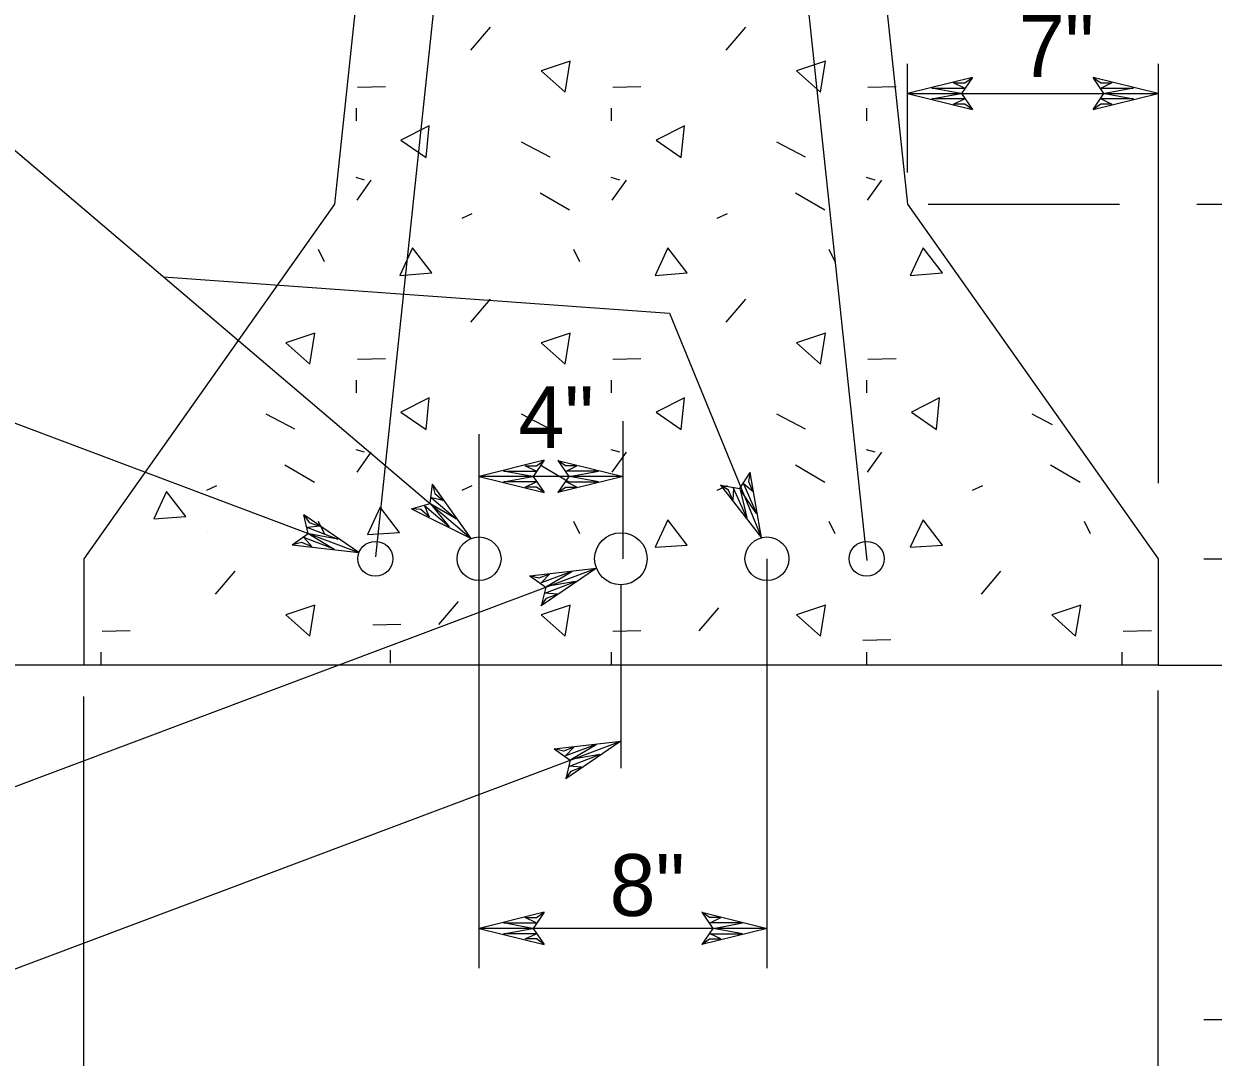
# Model space of a CAD drawing. Extents: x 504255 to 505955, y 659986 to 661086.
# Drawn here: x 504466.5 to 504576.9, y 660121 to 660217 of the extents above; entities that cross this region are included whole.
import ezdxf

# ---------------------------------------------------------------- set-up
doc = ezdxf.new("R2010")
doc.units = 0
for name, color, linetype in [('Level1', 7, 'Continuous'), ('Level3', 7, 'Continuous'), ('Level63', 7, 'Continuous')]:
    doc.layers.add(name, color=color, linetype=linetype)

msp = doc.modelspace()

# ---------------------------------------------------------------- linework, layer by layer
at = {"layer": 'Level1'}
for p, q in [((504548.54, 660203.18), (504548.54, 660213.27)), ((504571.81, 660213.27), (504571.81, 660174.33)), ((504459.95, 660210.08), (504508.05, 660169.2)), ((504548.54, 660210.51), (504571.81, 660210.51)), ((504550.46, 660200.24), (504568.25, 660200.24)), ((504575.42, 660200.24), (504641.43, 660200.24)), ((504552.13, 660193.73), (504552.13, 660193.73)), ((504446.93, 660186.96), (504497.61, 660167.89)), ((504522.14, 660167.32), (504522.14, 660180.1)), ((504508.77, 660129.3), (504508.77, 660178.87)), ((504522.14, 660174.95), (504508.77, 660174.95)), ((504535.51, 660129.3), (504535.51, 660167.32)), ((504576.05, 660167.32), (504615.42, 660167.32)), ((504459.29, 660143.76), (504519.66, 660166.46)), ((504571.81, 660165.85), (504571.81, 660165.85)), ((504521.94, 660164.9), (504521.94, 660147.89)), ((504571.81, 660094.57), (504571.81, 660155.1)), ((504472.07, 660094.57), (504472.07, 660154.53)), ((504456.67, 660125.86), (504521.93, 660150.4)), ((504535.51, 660133.01), (504508.77, 660133.01)), ((504576.05, 660124.54), (504607.76, 660124.54))]:
    msp.add_line(p, q, dxfattribs=at)
for points in [[(504515.94, 660325.64), (504499.16, 660167.49)], [(504527.95, 660325.64), (504544.77, 660167.15)], [(504501.68, 660259.96), (504495.34, 660200.24)], [(504542.2, 660259.96), (504548.54, 660200.24)], [(504554.58, 660212.01), (504548.54, 660210.51), (504554.58, 660209.01), (504553.87, 660209.52), (504552.82, 660209.52), (504553.83, 660210.01), (504550.81, 660210.01), (504553.5, 660210.51), (504550.81, 660211.01), (504553.83, 660211.01), (504552.82, 660211.51), (504553.87, 660211.51), (504554.58, 660212.01), (504553.57, 660210.51), (504554.58, 660209.01)], [(504565.78, 660209.01), (504571.81, 660210.51), (504565.78, 660212.01), (504566.49, 660211.51), (504567.53, 660211.51), (504566.52, 660211.01), (504569.54, 660211.01), (504566.86, 660210.51), (504569.54, 660210.01), (504566.52, 660210.01), (504567.53, 660209.52), (504566.49, 660209.52), (504565.78, 660209.01), (504566.78, 660210.51), (504565.78, 660212.01)], [(504495.34, 660200.24), (504472.07, 660167.32)], [(504548.54, 660200.24), (504571.81, 660167.32)], [(504479.47, 660193.49), (504526.44, 660190.12), (504534.98, 660169.27)], [(504514.81, 660176.46), (504508.77, 660174.96), (504514.81, 660173.47), (504514.1, 660173.97), (504513.06, 660173.97), (504514.06, 660174.47), (504511.05, 660174.47), (504513.73, 660174.96), (504511.05, 660175.46), (504514.06, 660175.46), (504513.06, 660175.96), (504514.1, 660175.96), (504514.81, 660176.46), (504513.81, 660174.96), (504514.81, 660173.47)], [(504516.09, 660176.45), (504522.14, 660174.95), (504516.09, 660173.46), (504516.81, 660173.95), (504517.85, 660173.95), (504516.85, 660174.45), (504519.86, 660174.45), (504517.18, 660174.95), (504519.86, 660175.45), (504516.85, 660175.45), (504517.85, 660175.95), (504516.81, 660175.95), (504516.09, 660176.45), (504517.1, 660174.95), (504516.09, 660173.46)], [(504531.18, 660174.14), (504534.98, 660169.27), (504533.94, 660175.34), (504533.78, 660174.5), (504534.19, 660173.55), (504533.32, 660174.27), (504534.54, 660171.53), (504533, 660173.76), (504533.62, 660171.12), (504532.4, 660173.87), (504532.34, 660172.75), (504531.93, 660173.7), (504531.18, 660174.14), (504532.97, 660173.84), (504533.94, 660175.34)], [(504502.49, 660171.96), (504508.05, 660169.2), (504504.45, 660174.23), (504504.66, 660173.39), (504505.45, 660172.72), (504504.36, 660172.99), (504506.65, 660171.04), (504504.29, 660172.4), (504506, 660170.29), (504503.7, 660172.24), (504504.14, 660171.21), (504503.36, 660171.88), (504502.49, 660171.96), (504504.23, 660172.45), (504504.45, 660174.23)], [(504491.43, 660168.61), (504497.61, 660167.89), (504492.51, 660171.41), (504492.99, 660170.69), (504493.96, 660170.33), (504492.84, 660170.21), (504495.66, 660169.15), (504492.98, 660169.63), (504495.32, 660168.22), (504492.49, 660169.28), (504493.25, 660168.46), (504492.28, 660168.83), (504491.43, 660168.61), (504492.91, 660169.66), (504492.51, 660171.41)], [(504472.07, 660167.32), (504472.07, 660157.45)], [(504571.81, 660167.32), (504571.81, 660157.45)], [(504513.48, 660165.74), (504519.66, 660166.46), (504514.55, 660162.94), (504515.04, 660163.66), (504516.01, 660164.03), (504514.89, 660164.14), (504517.71, 660165.21), (504515.03, 660164.73), (504517.37, 660166.13), (504514.54, 660165.07), (504515.3, 660165.89), (504514.33, 660165.52), (504513.48, 660165.74), (504514.96, 660164.69), (504514.55, 660162.94)], [(504571.81, 660157.45), (504472.07, 660157.45)], [(504515.75, 660149.68), (504521.93, 660150.4), (504516.82, 660146.88), (504517.31, 660147.61), (504518.28, 660147.97), (504517.16, 660148.08), (504519.98, 660149.15), (504517.29, 660148.67), (504519.64, 660150.07), (504516.81, 660149.01), (504517.56, 660149.83), (504516.6, 660149.46), (504515.75, 660149.68), (504517.23, 660148.63), (504516.82, 660146.88)], [(504514.81, 660134.51), (504508.77, 660133.01), (504514.81, 660131.52), (504514.1, 660132.02), (504513.06, 660132.02), (504514.06, 660132.51), (504511.05, 660132.51), (504513.73, 660133.01), (504511.05, 660133.51), (504514.06, 660133.51), (504513.06, 660134.01), (504514.1, 660134.01), (504514.81, 660134.51), (504513.81, 660133.01), (504514.81, 660131.52)], [(504529.46, 660134.51), (504535.51, 660133.01), (504529.46, 660131.52), (504530.18, 660132.02), (504531.22, 660132.02), (504530.22, 660132.51), (504533.23, 660132.51), (504530.55, 660133.01), (504533.23, 660133.51), (504530.22, 660133.51), (504531.22, 660134.01), (504530.18, 660134.01), (504529.46, 660134.51), (504530.47, 660133.01), (504529.46, 660131.52)]]:
    msp.add_lwpolyline(points, dxfattribs=at)
msp.add_lwpolyline([(504483.6, 660169.88), (504483.6, 660169.87), (504483.6, 660169.88)], close=True, dxfattribs=at)
at = {"layer": 'Level3'}
for p, q in [((504509.81, 660216.67), (504507.97, 660214.54)), ((504533.5, 660216.67), (504531.67, 660214.54)), ((504500.09, 660211.14), (504497.48, 660211.08)), ((504523.8, 660211.14), (504521.18, 660211.08)), ((504547.5, 660211.14), (504544.88, 660211.08)), ((504497.35, 660209.15), (504497.35, 660207.97)), ((504521.05, 660209.15), (504521.05, 660207.97)), ((504544.75, 660209.15), (504544.75, 660207.97)), ((504512.68, 660206.03), (504515.34, 660204.62)), ((504536.38, 660206.03), (504539.04, 660204.62)), ((504498.14, 660202.47), (504497.35, 660202.7)), ((504498.73, 660202.47), (504497.41, 660200.6)), ((504521.84, 660202.47), (504521.05, 660202.7)), ((504522.43, 660202.47), (504521.1, 660200.6)), ((504545.54, 660202.47), (504544.75, 660202.7)), ((504546.13, 660202.47), (504544.81, 660200.6)), ((504514.44, 660201.3), (504517.18, 660199.7)), ((504538.14, 660201.3), (504540.88, 660199.7)), ((504507.2, 660198.94), (504508.13, 660199.37)), ((504530.89, 660198.94), (504531.83, 660199.37)), ((504493.84, 660196.06), (504494.39, 660194.91)), ((504517.54, 660196.06), (504518.1, 660194.91)), ((504541.24, 660196.06), (504541.8, 660194.91)), ((504509.81, 660191.41), (504507.97, 660189.29)), ((504533.5, 660191.41), (504531.67, 660189.29)), ((504500.09, 660185.89), (504497.48, 660185.83)), ((504523.8, 660185.89), (504521.18, 660185.83)), ((504547.5, 660185.89), (504544.88, 660185.83)), ((504497.35, 660183.9), (504497.35, 660182.72)), ((504521.05, 660183.9), (504521.05, 660182.72)), ((504544.75, 660183.9), (504544.75, 660182.72)), ((504488.98, 660180.78), (504491.64, 660179.37)), ((504512.68, 660180.78), (504515.34, 660179.37)), ((504536.38, 660180.78), (504539.04, 660179.37)), ((504560.09, 660180.78), (504561.99, 660179.77)), ((504498.14, 660177.21), (504497.35, 660177.44)), ((504498.73, 660177.21), (504497.41, 660175.35)), ((504521.84, 660177.21), (504521.05, 660177.44)), ((504522.43, 660177.21), (504521.1, 660175.35)), ((504545.54, 660177.21), (504544.75, 660177.44)), ((504546.13, 660177.21), (504544.81, 660175.35)), ((504490.74, 660176.05), (504493.48, 660174.44)), ((504514.44, 660176.05), (504517.18, 660174.44)), ((504538.14, 660176.05), (504540.88, 660174.44)), ((504561.84, 660176.05), (504564.58, 660174.44)), ((504483.49, 660173.69), (504484.43, 660174.11)), ((504507.2, 660173.69), (504508.13, 660174.11)), ((504530.89, 660173.69), (504531.83, 660174.11)), ((504554.6, 660173.69), (504555.53, 660174.11)), ((504493.84, 660170.81), (504494.39, 660169.66)), ((504517.54, 660170.81), (504518.1, 660169.66)), ((504541.24, 660170.81), (504541.8, 660169.66)), ((504564.94, 660170.81), (504565.5, 660169.66)), ((504486.1, 660166.16), (504484.27, 660164.03)), ((504557.2, 660166.16), (504555.38, 660164.03)), ((504506.84, 660163.35), (504505, 660161.22)), ((504531.01, 660162.76), (504529.19, 660160.63)), ((504476.39, 660160.63), (504473.78, 660160.58)), ((504501.52, 660161.22), (504498.9, 660161.16)), ((504523.8, 660160.63), (504521.18, 660160.58)), ((504571.2, 660160.63), (504568.58, 660160.58)), ((504547.01, 660159.78), (504544.39, 660159.72)), ((504473.65, 660158.65), (504473.65, 660157.46)), ((504500.51, 660158.82), (504500.51, 660157.63)), ((504521.05, 660158.65), (504521.05, 660157.46)), ((504544.75, 660158.65), (504544.75, 660157.46)), ((504568.45, 660158.65), (504568.45, 660157.46))]:
    msp.add_line(p, q, dxfattribs=at)
for points in [[(504517.23, 660213.5), (504514.55, 660212.6), (504516.76, 660210.63)], [(504540.93, 660213.5), (504538.24, 660212.6), (504540.46, 660210.63)], [(504501.52, 660206.17), (504503.85, 660204.58), (504504.14, 660207.52)], [(504525.23, 660206.17), (504527.55, 660204.58), (504527.84, 660207.52)], [(504502.6, 660196.17), (504501.41, 660193.62), (504504.38, 660193.85)], [(504526.3, 660196.17), (504525.11, 660193.62), (504528.09, 660193.85)], [(504550, 660196.17), (504548.81, 660193.62), (504551.79, 660193.85)], [(504493.52, 660188.25), (504490.84, 660187.35), (504493.06, 660185.37)], [(504517.23, 660188.25), (504514.55, 660187.35), (504516.76, 660185.37)], [(504540.93, 660188.25), (504538.24, 660187.35), (504540.46, 660185.37)], [(504501.52, 660180.92), (504503.85, 660179.32), (504504.14, 660182.26)], [(504525.23, 660180.92), (504527.55, 660179.32), (504527.84, 660182.26)], [(504548.93, 660180.92), (504551.25, 660179.32), (504551.53, 660182.26)], [(504479.76, 660173.56), (504478.56, 660171.03), (504481.54, 660171.25)], [(504499.6, 660172.1), (504498.41, 660169.56), (504501.38, 660169.77)], [(504526.3, 660170.92), (504525.11, 660168.38), (504528.09, 660168.59)], [(504550, 660170.92), (504548.81, 660168.38), (504551.79, 660168.59)], [(504493.52, 660163), (504490.84, 660162.1), (504493.06, 660160.12)], [(504517.23, 660163), (504514.55, 660162.1), (504516.76, 660160.12)], [(504540.93, 660163), (504538.24, 660162.1), (504540.46, 660160.12)], [(504564.63, 660163), (504561.95, 660162.1), (504564.16, 660160.12)]]:
    msp.add_lwpolyline(points, close=True, dxfattribs=at)
at = {"layer": 'Level63'}
for q in [(504347.03, 660157.45), (504801.61, 660157.45)]:
    msp.add_line((504571.81, 660157.45), q, dxfattribs=at)
for centre, major_axis in [((504508.77, 660167.32), (-2.04, 0)), ((504521.94, 660167.32), (-2.44, 0)), ((504535.5, 660167.32), (-2.04, 0)), ((504499.14, 660167.32), (-1.63, 0)), ((504544.75, 660167.32), (1.63, 0))]:
    msp.add_ellipse(centre, major_axis=major_axis, ratio=0.99, dxfattribs=at)

# ---------------------------------------------------------------- texts
at = {"layer": 'Level1'}
for s, p in [('7"', (504558.89, 660212.05)), ('4"', (504512.44, 660177.6)), ('8"', (504520.89, 660134.16))]:
    msp.add_text(s, height=5.739, dxfattribs=at).set_placement(p)

doc.saveas('drawing.dxf')
